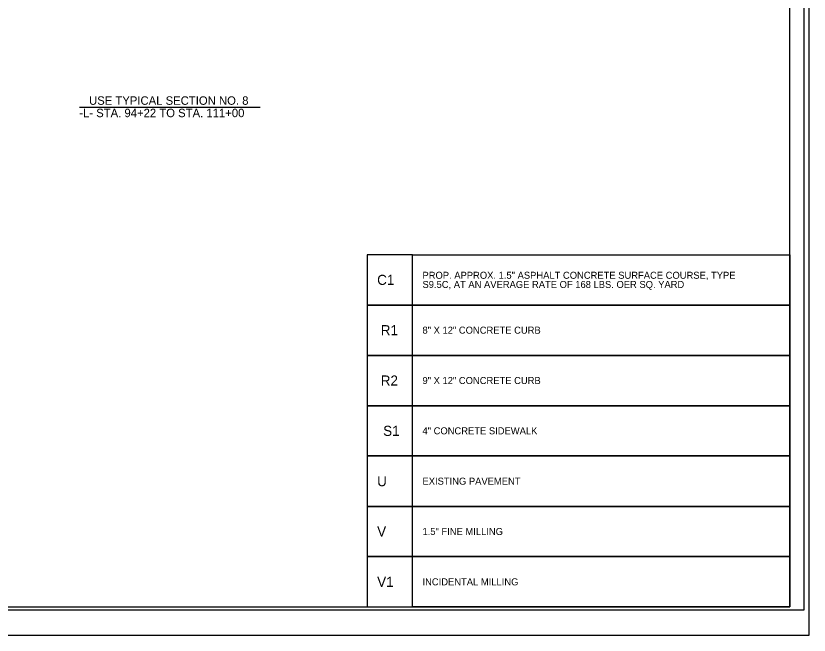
# Model space of a CAD drawing. Extents: x 1022283 to 1026986, y 174822 to 180471.
# Drawn here: x 1024733 to 1026493, y 174822 to 176197 of the extents above; entities that cross this region are included whole.
import ezdxf

# ---------------------------------------------------------------- set-up
doc = ezdxf.new("R2010")
doc.units = 0
for name, color, linetype in [('Prop Dimension', 7, 'Continuous'), ('Prop Pavement Schedule Description CELL', 7, 'Continuous'), ('Sheet Cutting Line CELL', 7, 'Continuous'), ('Sheet Plot Border Inside CELL', 7, 'Continuous'), ('Sheet Plot Border Outside CELL', 7, 'Continuous'), ('Sheet Typical CELL', 7, 'Continuous'), ('Typical Text Label CELL', 7, 'Continuous')]:
    doc.layers.add(name, color=color, linetype=linetype)

msp = doc.modelspace()

# ---------------------------------------------------------------- linework, layer by layer
at = {"layer": 'Prop Pavement Schedule Description CELL'}
for points in [[(1025612.6, 175667.2), (1026450.7, 175667.2), (1026450.7, 175555.4), (1025612.6, 175555.4), (1025612.6, 175667.2), (1025512, 175667.2), (1025512, 175555.4), (1025612.6, 175555.4)], [(1025612.6, 175555.4), (1026450.7, 175555.4), (1026450.7, 175443.7), (1025612.6, 175443.7), (1025612.6, 175555.4), (1025512, 175555.4), (1025512, 175443.7), (1025612.6, 175443.7)], [(1025612.6, 175443.7), (1026450.7, 175443.7), (1026450.7, 175331.9), (1025612.6, 175331.9), (1025612.6, 175443.7), (1025512, 175443.7), (1025512, 175331.9), (1025612.6, 175331.9)], [(1025612.6, 175331.9), (1026450.7, 175331.9), (1026450.7, 175220.2), (1025612.6, 175220.2), (1025612.6, 175331.9), (1025512, 175331.9), (1025512, 175220.2), (1025612.6, 175220.2)], [(1025612.6, 175220.2), (1026450.7, 175220.2), (1026450.7, 175108.4), (1025612.6, 175108.4), (1025612.6, 175220.2), (1025512, 175220.2), (1025512, 175108.4), (1025612.6, 175108.4)], [(1025612.6, 175108.4), (1026450.7, 175108.4), (1026450.7, 174996.7), (1025612.6, 174996.7), (1025612.6, 175108.4), (1025512, 175108.4), (1025512, 174996.7), (1025612.6, 174996.7)], [(1025612.6, 174996.7), (1026450.7, 174996.7), (1026450.7, 174885), (1025612.6, 174885), (1025612.6, 174996.7), (1025512, 174996.7), (1025512, 174885), (1025612.6, 174885)]]:
    msp.add_lwpolyline(points, dxfattribs=at)
at = {"layer": 'Sheet Cutting Line CELL'}
msp.add_line((1022283.2, 174822.5), (1026493.2, 174822.5), dxfattribs=at)
at = {"layer": 'Sheet Plot Border Inside CELL'}
msp.add_lwpolyline([(1026482, 177516.3), (1022315.7, 177516.3), (1022315.7, 174878.6), (1026482, 174878.6)], close=True, dxfattribs=at)
at = {"layer": 'Sheet Plot Border Outside CELL'}
msp.add_lwpolyline([(1026493.2, 177572.5), (1022283.2, 177572.5), (1022283.2, 174822.5), (1026493.2, 174822.5)], close=True, dxfattribs=at)
at = {"layer": 'Sheet Typical CELL'}
msp.add_lwpolyline([(1026450.7, 177510), (1022700.7, 177510), (1022700.7, 174885), (1026450.7, 174885)], close=True, dxfattribs=at)
at = {"layer": 'Typical Text Label CELL'}
msp.add_line((1024873.5, 175994.5), (1025275, 175994.5), dxfattribs=at)

# ---------------------------------------------------------------- texts
at = {"layer": 'Prop Dimension'}
msp.add_text('-L- STA. 94+22 TO STA. 111+00', height=18.75, dxfattribs=at).set_placement((1024873.2, 175972.5))
at = {"layer": 'Prop Pavement Schedule Description CELL'}
for s, height, p in [('C1', 22.35, (1025534.4, 175600.1)), ('PROP. APPROX. 1.5" ASPHALT CONCRETE SURFACE COURSE, TYPE ', 15.576, (1025635, 175613.7)), ('S9.5C, AT AN AVERAGE RATE OF 168 LBS. OER SQ. YARD', 15.576, (1025635, 175593.3)), ('R1', 22.35, (1025542.4, 175488.4)), ('8" X 12" CONCRETE CURB', 15.576, (1025635, 175491.8)), ('R2', 22.35, (1025542.4, 175376.6)), ('9" X 12" CONCRETE CURB', 15.576, (1025635, 175380)), ('S1', 22.35, (1025547.7, 175264.9)), ('4" CONCRETE SIDEWALK', 15.576, (1025635, 175268.3)), ('U', 22.3, (1025534.4, 175153.1)), ('EXISTING PAVEMENT', 15.576, (1025635, 175156.5)), ('V', 22.3, (1025534.4, 175041.4)), ('1.5" FINE MILLING', 15.576, (1025635, 175044.8)), ('V1', 22.35, (1025534.4, 174929.6)), ('INCIDENTAL MILLING', 15.576, (1025635, 174933))]:
    msp.add_text(s, height=height, dxfattribs=at).set_placement(p)
at = {"layer": 'Typical Text Label CELL'}
msp.add_text('USE TYPICAL SECTION NO. 8', height=18.75, dxfattribs=at).set_placement((1024894.9, 176000))

doc.saveas('drawing.dxf')
